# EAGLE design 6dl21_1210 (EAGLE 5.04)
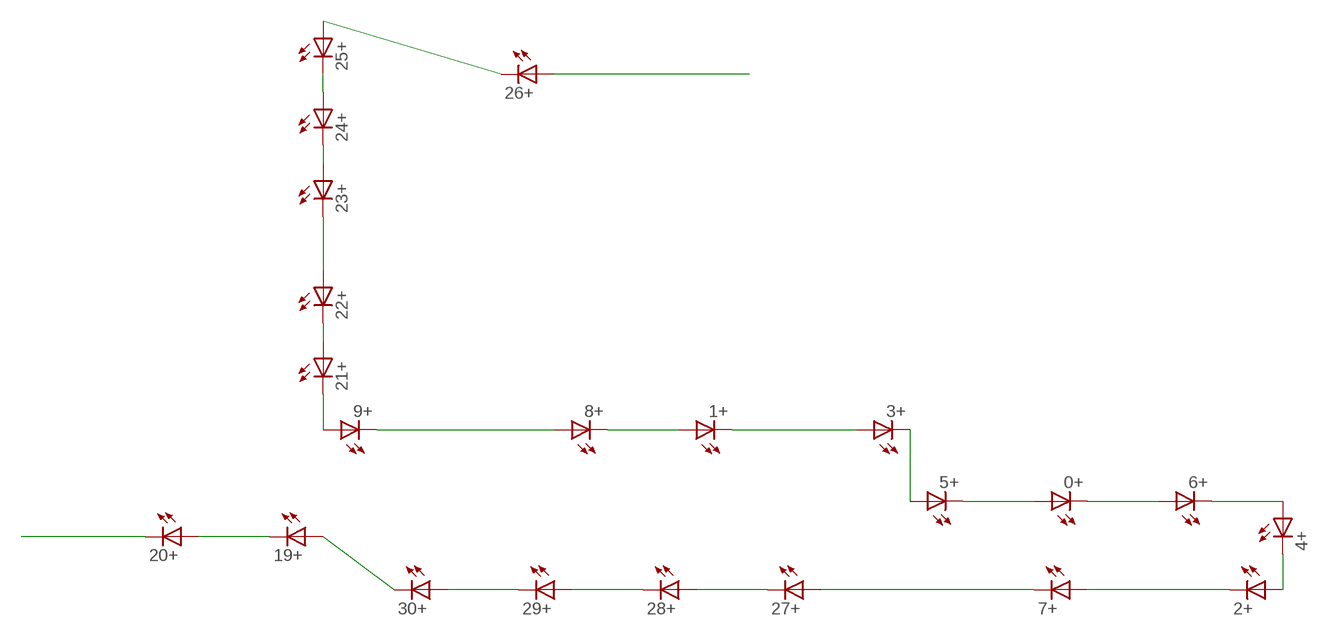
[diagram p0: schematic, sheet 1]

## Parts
0+  LED1210  [1210]
1+  LED1210  [1210]
2+  LED1210  [1210]
3+  LED1210  [1210]
4+  LED1210  [1210]
5+  LED1210  [1210]
6+  LED1210  [1210]
7+  LED1210  [1210]
8+  LED1210  [1210]
9+  LED1210  [1210]
19+  LED1210  [1210]
20+  LED1210  [1210]
21+  LED1210  [1210]
22+  LED1210  [1210]
23+  LED1210  [1210]
24+  LED1210  [1210]
25+  LED1210  [1210]
26+  LED1210  [1210]
27+  LED1210  [1210]
28+  LED1210  [1210]
29+  LED1210  [1210]
30+  LED1210  [1210]

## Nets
MINUS: 20+.P$2(C)
N$2: 19+.P$2(C) 20+.P$1(A)
N$4: 19+.P$1(A) 30+.P$2(C)
N$6: 8+.P$1(A) 9+.P$2(C)
N$7: 29+.P$2(C) 30+.P$1(A)
N$8: 28+.P$2(C) 29+.P$1(A)
N$9: 27+.P$2(C) 28+.P$1(A)
N$12: 2+.P$2(C) 7+.P$1(A)
N$13: 7+.P$2(C) 27+.P$1(A)
N$14: 2+.P$1(A) 4+.P$2(C)
N$15: 4+.P$1(A) 6+.P$2(C)
N$16: 0+.P$2(C) 6+.P$1(A)
N$17: 0+.P$1(A) 5+.P$2(C)
N$18: 3+.P$2(C) 5+.P$1(A)
N$19: 1+.P$2(C) 3+.P$1(A)
N$20: 1+.P$1(A) 8+.P$2(C)
N$23: 9+.P$1(A) 21+.P$2(C)
N$24: 21+.P$1(A) 22+.P$2(C)
N$25: 22+.P$1(A) 23+.P$2(C)
N$26: 24+.P$1(A) 25+.P$2(C)
N$27: 25+.P$1(A) 26+.P$2(C)
N$28: 23+.P$1(A) 24+.P$2(C)
PLUS: 26+.P$1(A)

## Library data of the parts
0+ 1+ 2+ 3+ 4+ 5+ 6+ 7+ 8+ 9+ 19+ 20+ 21+ 22+ 23+ 24+ 25+ 26+ 27+ 28+ 29+ 30+ = led(2):LED: LED

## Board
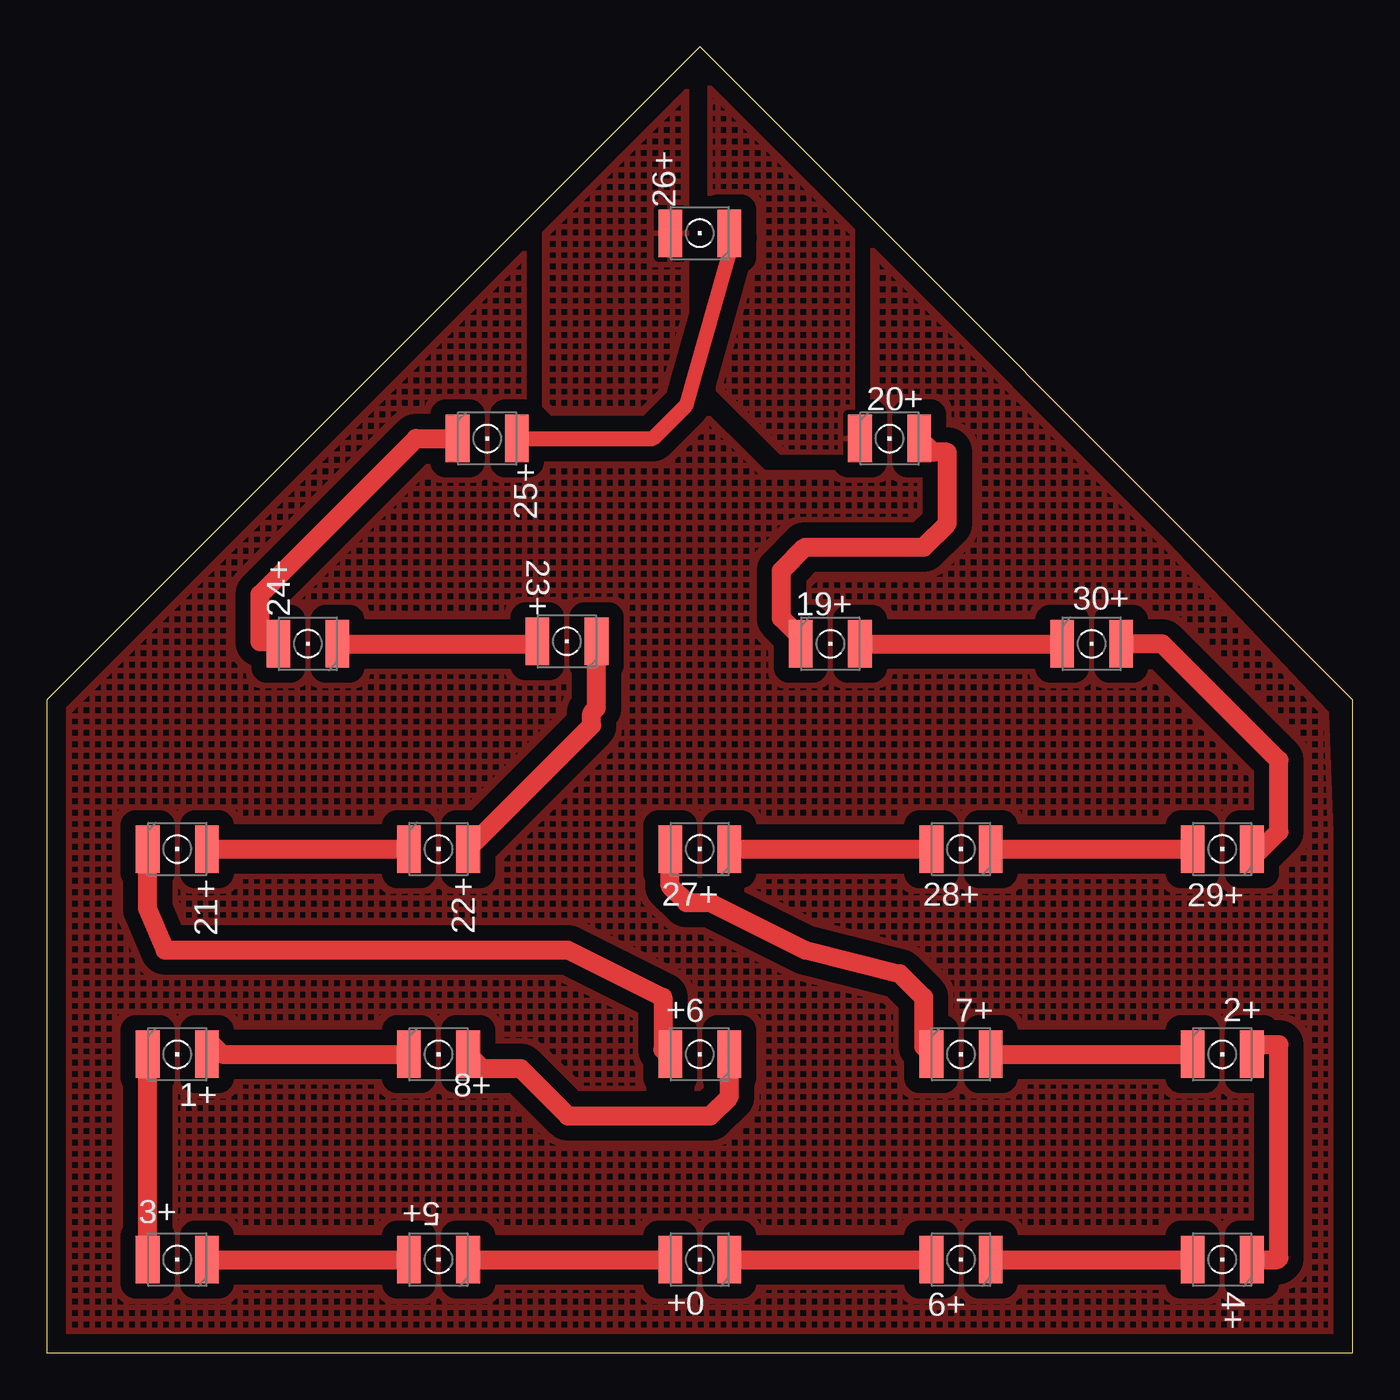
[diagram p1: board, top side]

Size 70 x 70 mm. Coordinates in mm from the lower left corner, seen from the top.
Outline: 0,0 70,0 70,35 35,70 0,35 0,0
Copper layers (1*16): Top 0.035mm / dielectric 1.5mm / Bottom 0.035mm
Design rules "default": minimum track width 10mil, minimum drill 24mil, track to track 8mil, track to pad 8mil, pad to pad 8mil, via to via 8mil, smd to smd 8mil, copper to edge 40mil, drill to drill 8mil, minimum pad ring 10mil, minimum via ring 8mil, stop-mask expansion 4mil, vias tented up to drill 0mil, thermal gap 10mil

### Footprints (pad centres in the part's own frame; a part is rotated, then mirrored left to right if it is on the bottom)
1210 = smd 1.27 x 2.54: P$1 1.587,0; P$2 -1.587,0

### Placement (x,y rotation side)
0+  35,5 180 top
1+  7,16 0 top
2+  63,16 0 top
3+  7,5 180 top
4+  63,5 180 top
5+  21,5 180 top
6+  49,5 180 top
7+  49,16 0 top
8+  21,16 0 top
9+  35,16 180 top
19+  42,38 0 top
20+  45.17,49 0 top
21+  7,27 0 top
22+  21,27 0 top
23+  27.88,38.13 180 top
24+  14,38 180 top
25+  23.61,49 0 top
26+  35,60 180 top
27+  35,27 180 top
28+  49,27 180 top
29+  63,27 180 top
30+  56,38 0 top

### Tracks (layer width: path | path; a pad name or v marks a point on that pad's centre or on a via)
MINUS
  pour Top (isolate 0.813, hatched): 35.56,68.58 35.56,52.07 39.37,48.26 43.18,48.26 43.18,60.96
N$1
  pour Top (isolate 0.813, rank 3, hatched): 34.29,69.85 0,34.29 0,0 69.85,0 68.58,34.29 45.72,58.42
N$2
  Top 1.016: 19+.P$2 40.41,38.33 39.37,39.37 39.37,41.91 40.64,43.18 46.99,43.18 48.26,44.45 48.26,48.26 47.5,48.26 20+.P$1
N$4
  Top 1.016: 19+.P$1 30+.P$2
N$6
  Top 1.016: 9+.P$2 36.59,13.73 35.56,12.7 27.94,12.7 25.4,15.24 23.35,15.24 8+.P$1
N$7
  Top 1.016: 30+.P$1 59.79,38 66.04,31.75 66.04,27.94 64.77,26.67 64.77,26.82 29+.P$2
N$8
  Top 1.016: 28+.P$2 29+.P$1
N$9
  Top 1.016: 27+.P$2 28+.P$1
N$12
  Top 1.016: 7+.P$1 2+.P$2
N$13
  Top 1.016: 27+.P$1 33.41,25.01 34.29,24.13 35.56,24.13 40.64,21.59 45.72,20.32 46.99,19.05 46.99,16.42 7+.P$2
N$14
  Top 1.016: 4+.P$2 65.96,5 66.04,5.08 66.04,16.51 65.1,16.51 2+.P$1
N$15
  Top 1.016: 6+.P$2 4+.P$1
N$16
  Top 1.016: 0+.P$2 6+.P$1
N$17
  Top 1.016: 5+.P$2 0+.P$1
N$18
  Top 1.016: 3+.P$2 5+.P$1
N$19
  Top 1.016: 3+.P$1 1+.P$2
N$20
  Top 1.016: 8+.P$2 9.4,16 8.89,16.51 8.89,16.3 1+.P$1
N$23
  Top 1.016: 21+.P$2 5.41,23.8 6.35,21.59 27.94,21.59 33.02,19.05 33.02,16.24 9+.P$1
N$24
  Top 1.016: 21+.P$1 22+.P$2
N$25
  Top 1.016: 23+.P$2 29.47,34.55 29.21,34.29 29.21,33.62 22+.P$1
N$26
  Top 1.016: 25+.P$2 19.79,49 11.43,40.64 11.43,38.1 12.31,38.1 24+.P$1
N$27
  Top 0.305: 36.83,59.76 26+.P$2
  Top 0.813: 25+.P$1 32.49,49 34.29,50.8 36.83,59.76
N$28
  Top 1.016: 24+.P$2 26.16,38 23+.P$1
PLUS
  pour Top (isolate 0.813, hatched): 34.29,68.58 34.29,52.07 31.75,49.53 27.94,49.53 26.67,50.8 26.67,60.96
